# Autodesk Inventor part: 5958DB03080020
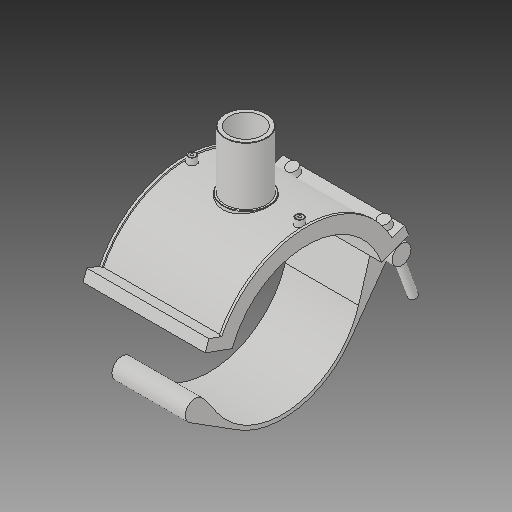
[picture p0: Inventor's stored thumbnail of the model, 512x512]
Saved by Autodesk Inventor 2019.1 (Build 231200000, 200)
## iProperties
Created: 2017-07
Part Number: 5958DB03080020
Material: Generic
Description: PLASSON BRANCH SADDLE 8''DIPS x 2''IPS
Document SubType Name: Modeling
Designer: KIM
Mass: 764.267 g
Surface Area: 1930.38 cm^2
Volume: 764.267 cm^3
Density: 1 g/cm^3
Appearance: Default
Author: KIM
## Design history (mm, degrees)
derived "5958D (2).ipt"
feature "Solid6::5958D (2).ipt"
tag "TaggingFeature1"
body "Solid1"
other parameters: "d_" = 228.9, "d1" = 60.1, "B_" = 179.832, "H_" = 104.902, "H1" = 84.074, "L" = 176.022, "t" = 6, "d244" = 228.9, "d245" = 20.828, "d248" = 179.832, "d249" = 89.916, "d252" = 114.45, "d254" = 20.828, "d256" = 539.496, "d257" = 28.6125, "d258" = 269.748, "d259" = 0.5, "d260" = 176.022, "d261" = 0, "d287" = 136.11112, "d288" = 66.11, "d290" = 0, "d291" = 219.352, "d292" = 60.1, "d294" = 0, "d309" = 144.45, "d310" = 12, "d311" = 12, "d315" = 3 deg, "d316" = 4, "d318" = 4, "d320" = 14, "d321" = 0, "d331" = 0.601, "d332" = 48.08, "d334" = 0, "d337" = 0.601, "d340" = 10.56132, "d341" = 10.56132, "d342" = 20 deg, "d343" = 20 deg, "d344" = 719.328, "d345" = 228.9, "d347" = 0, "d352" = 41.656, "d353" = 16.023, "d355" = 0, "d356" = 20 deg, "d357" = 34.335, "d358" = 228.9, "d359" = 240.345, "d360" = 27.468, "d361" = 10 deg, "d362" = 9.26846, "d363" = 45.78, "d366" = 125.895, "d367" = 9.68502, "d368" = 105.6132, "d369" = 0, "d370" = 158.4198, "d371" = 0, "d372" = 132.0165, "d374" = 11.445, "d375" = 16.023, "d376" = 11.445, "d377" = 16.023, "d378" = 114.45, "d379" = 0, "d380" = 9.6138, "d381" = 0, "d383" = 145.692, "d384" = 17.6022, "d385" = 2.289, "d386" = 3.52044, "d387" = 0, "d389" = 360 deg
